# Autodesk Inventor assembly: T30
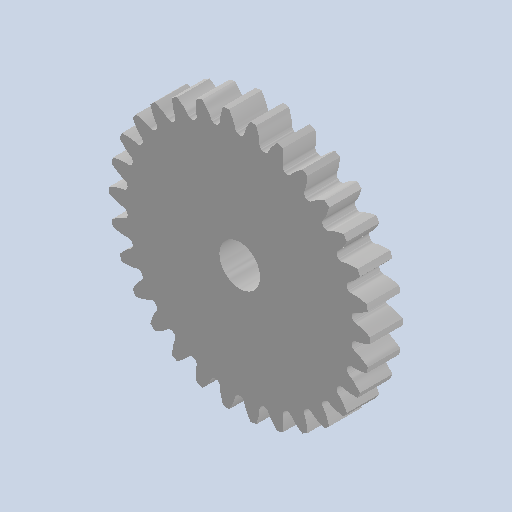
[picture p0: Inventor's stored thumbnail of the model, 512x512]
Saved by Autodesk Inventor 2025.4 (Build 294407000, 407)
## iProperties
Created: 2026-05
Part Number: T30
Document SubType Name: Assembly
Designer: AdminForWorker
Title: T30 v1
Author: AdminForWorker
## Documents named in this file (2)
- c:\worker\convert-fusion-r03-cosv3\tmp\job-1\19\temp\files\92d14950-10c5-4624-904e-78b88416050a\ef524a12-1ffc-47dc-90c2-a0651fe4bd4b.iam
- c:\worker\convert-fusion-r03-cosv3\tmp\job-1\19\temp\files\92d14950-10c5-4624-904e-78b88416050a\Spur Gear 30 teeth.ipt
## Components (1 placed, 1 different names)
1. Spur Gear 30 teeth:1
